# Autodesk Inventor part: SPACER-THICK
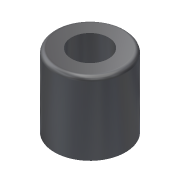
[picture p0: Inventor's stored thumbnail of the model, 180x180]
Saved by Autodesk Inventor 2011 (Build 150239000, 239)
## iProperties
Created: 2007-08
Part Number: SPACER-THICK
Material: Delrin, Black
Document SubType Name: Modeling
Density: 1.425 g/cm^3
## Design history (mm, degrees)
feature "Base1"
body "Solid1"
